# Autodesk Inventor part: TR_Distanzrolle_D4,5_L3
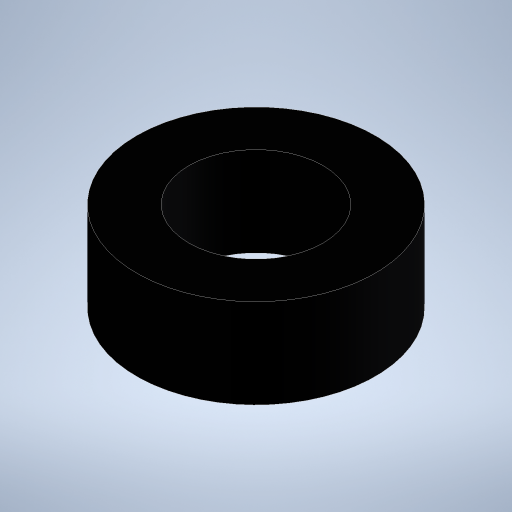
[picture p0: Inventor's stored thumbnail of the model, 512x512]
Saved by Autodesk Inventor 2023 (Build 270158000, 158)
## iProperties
Created: 2023-11
Part Number: TR_Distanzrolle_D4,5_L3
Material: PC/ABS-Kunststoff
Document SubType Name: Modeling
Designer: Admin
Density: 0.357273 g/cm^3
Appearance: Glatt - Schwarz
Author: Admin
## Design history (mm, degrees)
sketch "Skizze1"
  geometry: C1 r 2.25 at (0, 0); C2 r 4 at (0, 0); 1 further point
  constraints: 2 centre point, 2 coincident
  dimensions: "d0" = 4.5 diameter of C1; "d1" = 8 diameter of C2
extrude "Extrusion1" new body sketch "Skizze1" distance "d2" = 3; taper "d3" = 0 deg
node "Volumenkörper1"
